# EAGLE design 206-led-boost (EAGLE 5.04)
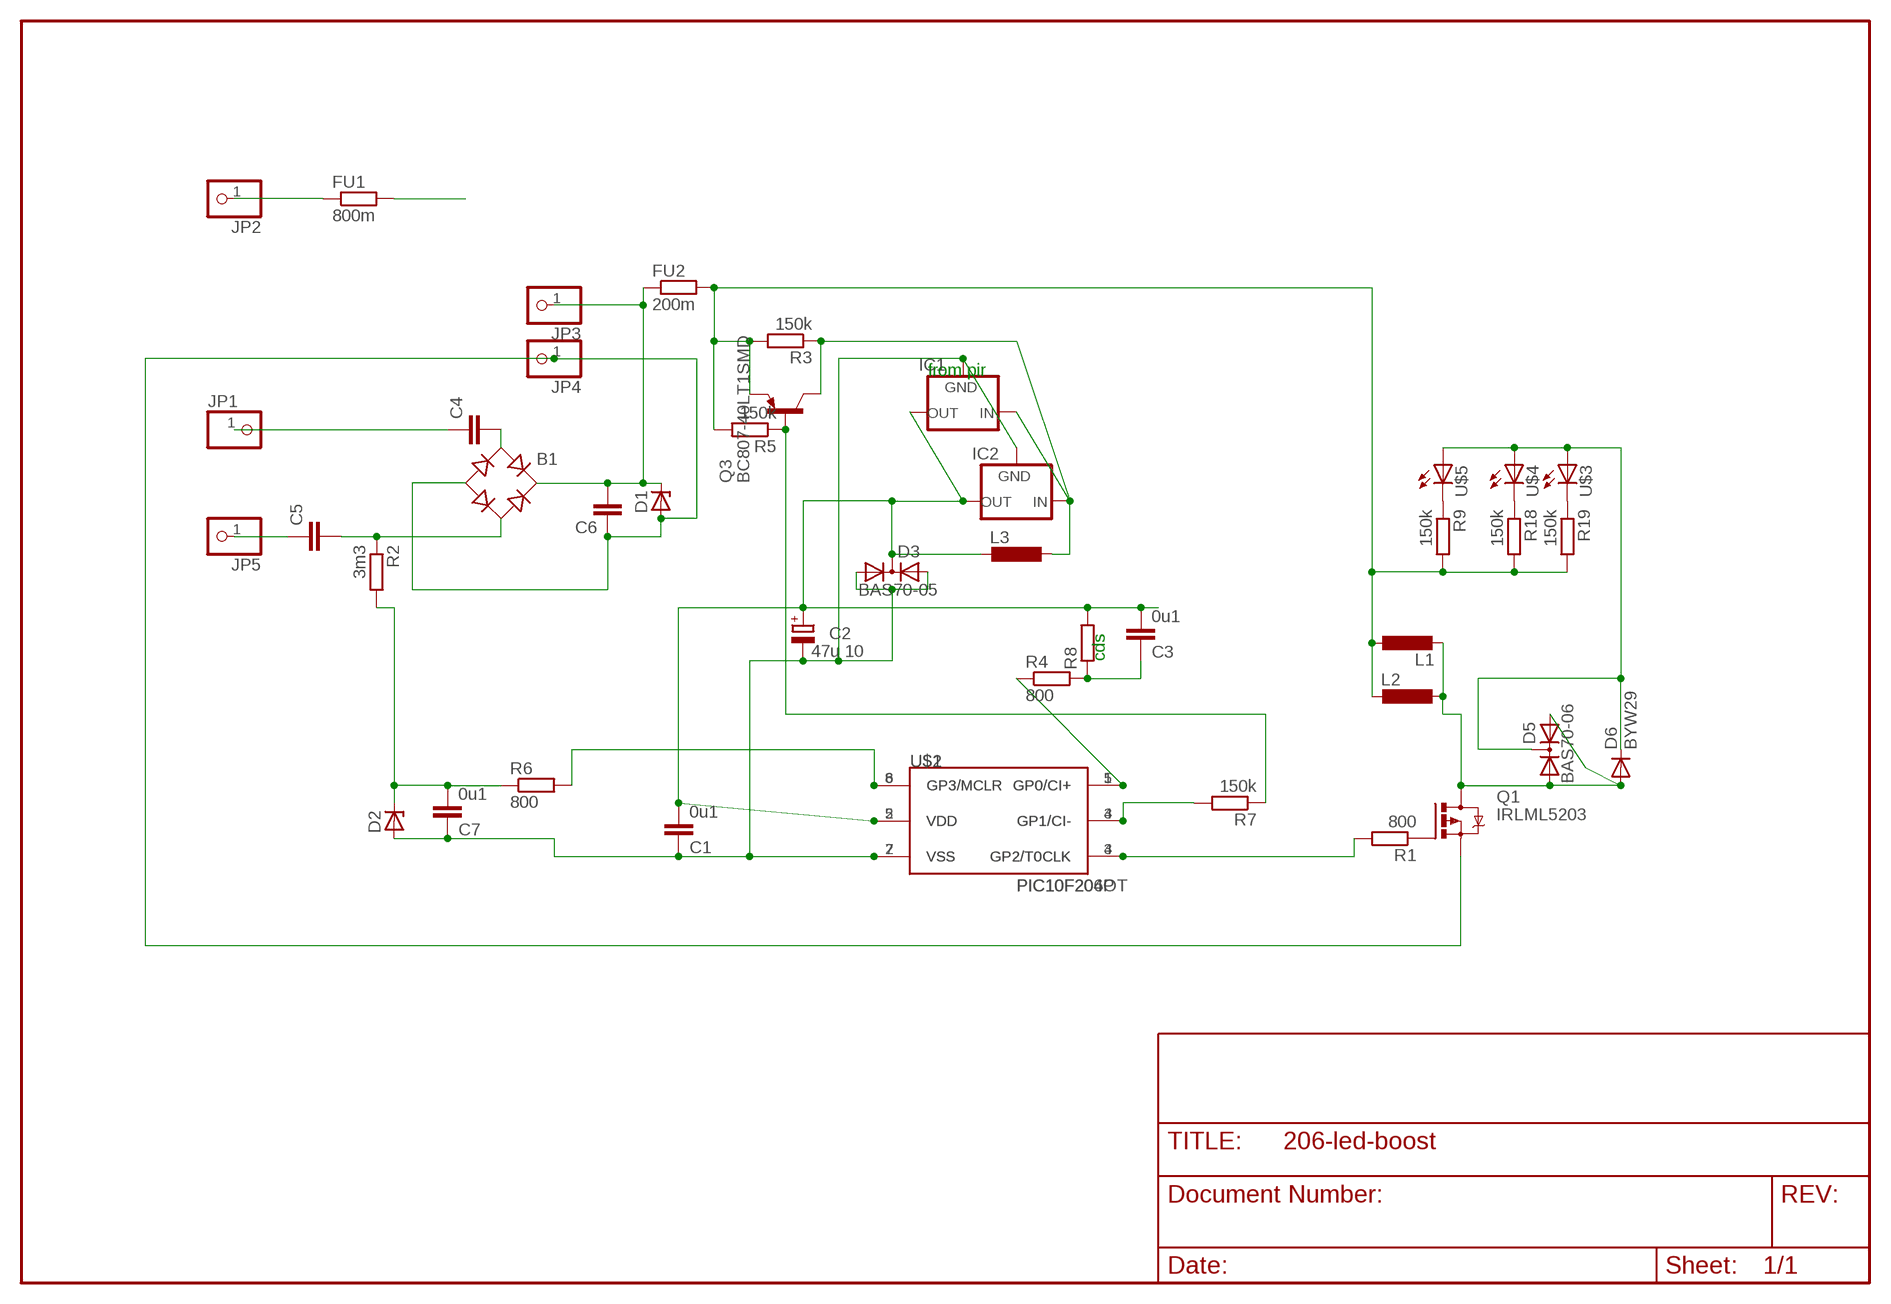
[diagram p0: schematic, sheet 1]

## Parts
B1  RB1A  [RB1A]
C1  0u1  C-EUC1206  [C1206]
C2  47u 10  CPOL-EUE2.5-5  [E2,5-5]
C3  0u1  C-EUC1206  [C1206]
C4  C-EU050-025X075  [C050-025X075]
C5  C-EU050-025X075  [C050-025X075]
C6  C-EU050-025X075  [C050-025X075]
C7  0u1  C-EUC1206  [C1206]
D1  ZENER-DIODEZD-7.5  [ZDIO-7.5]
D2  ZENER-DIODESOT23  [SOT23]
D3  BAS70-05  [SOT23]
D5  BAS70-06  [SOT23]
D6  BYW29  [DO220S]
FU1  800m  R-EU_0204/5  [0204/5]
FU2  200m  R-EU_0204/5  [0204/5]
IC1  XC63FPT  [TO92]
IC2  XC63FPP  [SOT89R]
JP1  PINHD-1X1  [1X01]
JP2  PINHD-1X1  [1X01]
JP3  PINHD-1X1  [1X01]
JP4  PINHD-1X1  [1X01]
JP5  PINHD-1X1  [1X01]
L1  L-EUL5650M  [L5650M]
L2  L-EU0207/7  [0207/7]
L3  L-EU0207/7  [0207/7]
Q1  IRLML5203  [MICRO3]
Q3  BC807-40LT1SMD  [SOT23-BEC]
R1  800  R-EU_R1206  [R1206]
R2  3m3  R-EU_R1206  [R1206]
R3  150k  R-EU_R1206  [R1206]
R4  800  R-EU_R1206  [R1206]
R5  150k  R-EU_R1206  [R1206]
R6  800  R-EU_R1206  [R1206]
R7  150k  R-EU_R1206  [R1206]
R8  R-EU_0207/5V  [0207/5V]
R9  150k  R-EU_R1206  [R1206]
R18  150k  R-EU_R1206  [R1206]
R19  150k  R-EU_R1206  [R1206]
U$1  PIC10F206P  [DIL8]
U$2  PIC10F204OT  [SOT23-6]
U$3  LED5MM  [LED5MM]
U$4  LED5MM  [LED5MM]
U$5  LED5MM  [LED5MM]

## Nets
N$1: B1.+ C6.2 D1.C FU2.1 JP3.1
N$4: FU1.1 JP2.1
N$6: C1.1 C2.- C7.1 D2.1(A) D3.1(A1) D3.2(A2) IC1.1(GND) IC2.1(GND) U$1.7(VSS) U$2.2(VSS)
N$7: D5.3(C) D6.C U$3.A U$4.A U$5.A
N$8: B1.- C6.1 D1.A JP4.1 Q1.2(S)
N$9: FU1.2
N$10: Q1.1(G) R1.1
N$11: Q3.B R5.1 R7.1
N$12: R6.2 U$1.8(GP3/MCLR) U$2.6(GP3/MCLR)
N$13: R7.2 U$1.4(GP1/CI-) U$2.3(GP1/CI-)
N$14: R1.2 U$1.3(GP2/T0CLK) U$2.4(GP2/T0CLK)
N$15: IC1.2(IN) IC2.2(IN) L3.1 Q3.C R3.1
N$16: C7.2 D2.3(C) R2.2 R6.1
N$17: C5.1 JP5.1
N$18: B1.AC2 C5.2 R2.1
N$19: FU2.2 L1.1 L2.2 Q3.E R3.2 R5.2 R9.2 R18.2 R19.2
N$20: C4.1 JP1.1
N$23: C3.1 R4.2 R8.1
N$26: D5.1(A1) D5.2(A2) D6.A L1.2 L2.1 Q1.3(D)
N$29: R4.1 U$1.5(GP0/CI+) U$2.1(GP0/CI+)
N$33: B1.AC1 C4.2
N$38: R9.1 U$5.K(C)
N$54: R18.1 U$4.K(C)
N$55: R19.1 U$3.K(C)
V2CC: C1.2 C2.+ C3.2 D3.3(C) IC1.3(OUT) IC2.3(OUT) L3.2 R8.2 U$1.2(VDD) U$2.5(VDD)

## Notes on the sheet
- from pir
- cds

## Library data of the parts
B1 = rectifier:RB1A: RECTIFIER 1 A
C1 C3-C7 = rcl:C-EU: CAPACITOR, European symbol
C2 = rcl:CPOL-EU: POLARIZED CAPACITOR, European symbol
D1 D2 = diode-1:ZENER-DIODE: Z-Diode
D3 = diode-1:BAS70-05: Silicon Schottky Diodes General-purpose diode for high-speed switching
D5 = diode-1:BAS70-06: Silicon Schottky Diodes General-purpose diode for high-speed switching
D6 = diode:BYW29: DIODE
FU1 FU2 R1-R7 R9 R18 R19 = rcl:R-EU_: RESISTOR, European symbol
IC1 IC2 = v-reg:XC63FP: Positiv Voltage Regulators www.torex.co.jp/english/product/pro02/pdf/0201_xc62fp.pdf
JP1-JP5 = pinhead:PINHD-1X1: PIN HEADER
L1 = rcl-2:L-EU: INDUCTOR, European symbol
L2 L3 = rcl:L-EU: INDUCTOR, European symbol
Q1 = transistor-power:IRLML5203: HEXFET P-Channel Power MOSFET
Q3 = transistor-pnp:BC807*: PNP Transistror
R8 = rcl(2):R-EU_: RESISTOR, European symbol
U$1 U$2 = microchip-3:PIC10F2*: uPC nW 0,25/0,5k Program Flash memory Comparator
U$3-U$5 = led(3):LED: LED

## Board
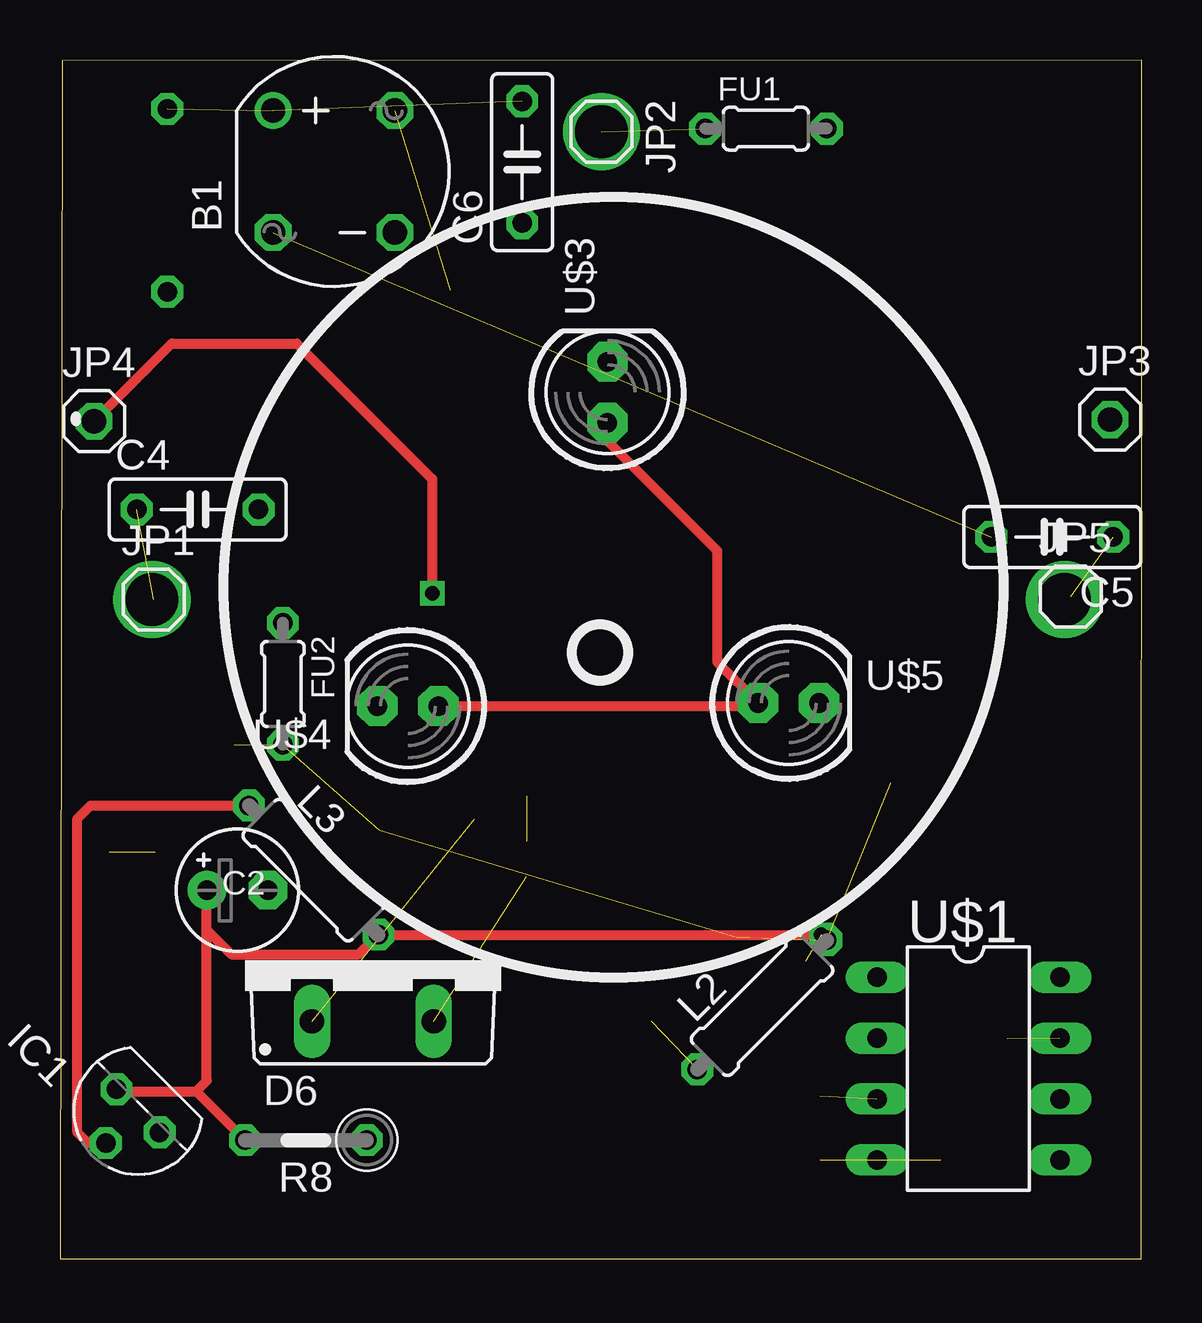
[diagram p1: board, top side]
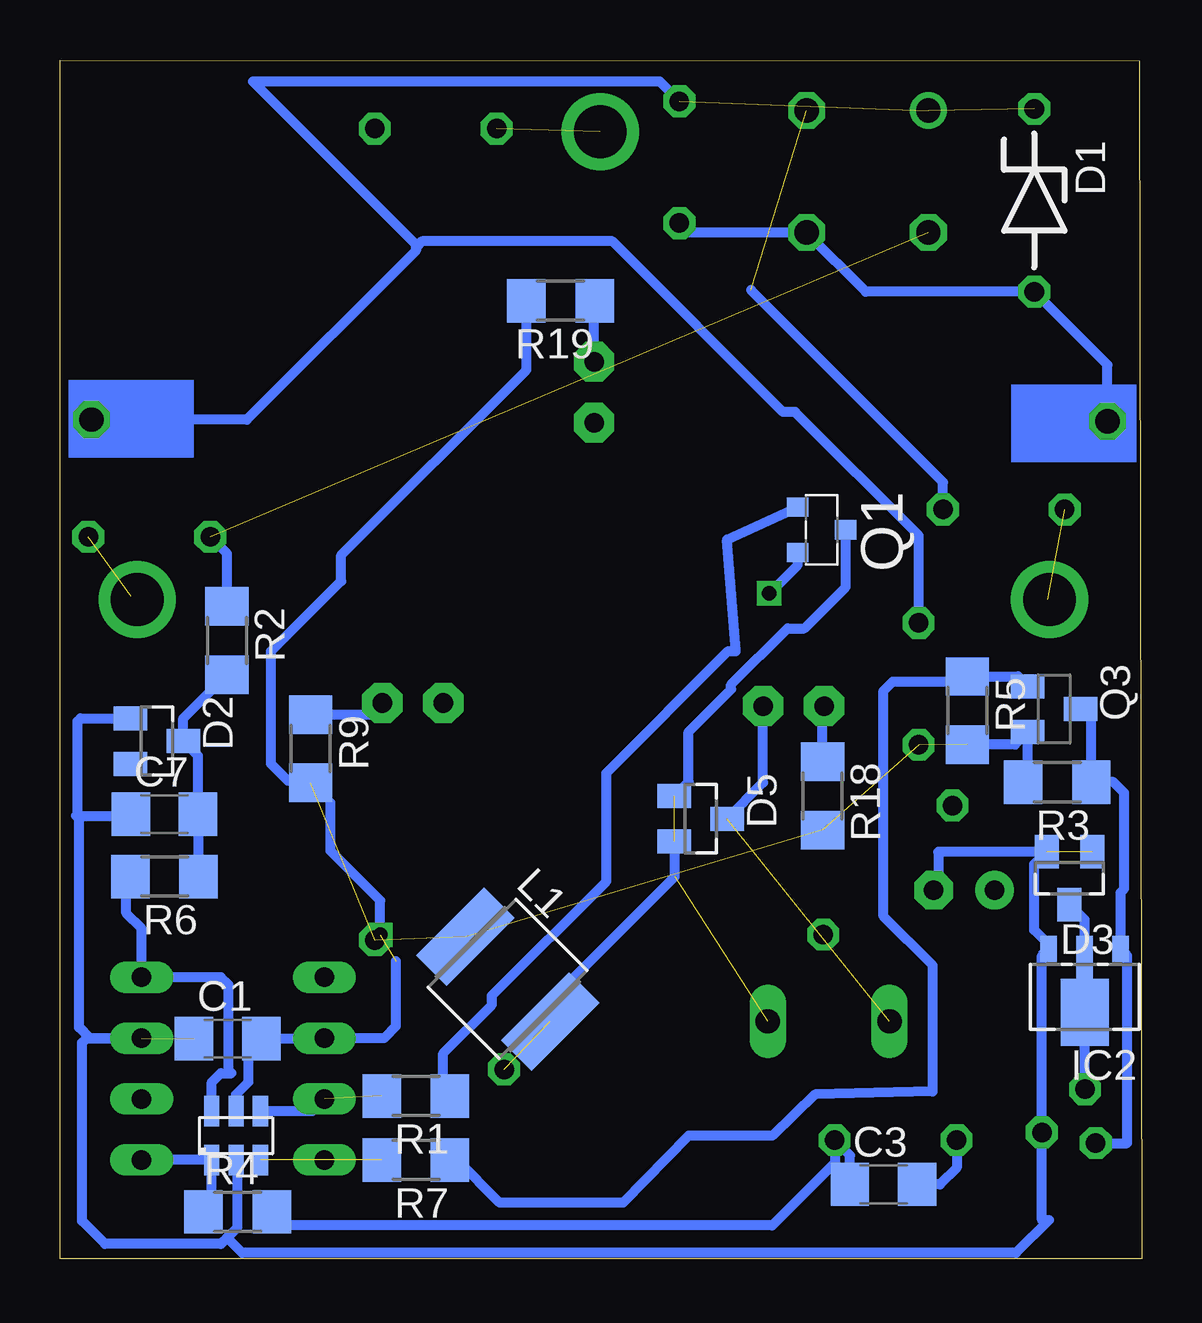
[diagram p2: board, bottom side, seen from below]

Size 45.09 x 49.97 mm. Coordinates in mm from the lower left corner, seen from the top.
Outline: 0,0 45.07,0 45.08,49.97 0.09,49.94 0,0
Copper layers (1*16): Top 0.035mm / dielectric 1.5mm / Bottom 0.035mm
Design rules "default": minimum track width 10mil, minimum drill 24mil, track to track 8mil, track to pad 8mil, pad to pad 8mil, via to via 8mil, smd to smd 8mil, copper to edge 40mil, drill to drill 8mil, minimum pad ring 10mil, minimum via ring 8mil, stop-mask expansion 4mil, vias tented up to drill 0mil, thermal gap 10mil

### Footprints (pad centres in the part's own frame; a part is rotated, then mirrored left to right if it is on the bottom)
RB1A = drill 1.016 round: + -2.54,2.54 | drill 1.016 octagon: - 2.54,-2.54; AC1 2.54,2.54; AC2 -2.54,-2.54
C1206 = smd 1.6 x 1.8: 1 -1.4,0; 2 1.4,0
E2,5-5 = drill 0.813 pad 1.6 round: + -1.27,0 | drill 0.813 pad 1.6 octagon: - 1.27,0
C050-025X075 = drill 0.813 octagon: 1 -2.54,0; 2 2.54,0
ZDIO-7.5 = drill 0.813 octagon: A 3.81,0; C -3.81,0
SOT23 = smd 1 x 1.4: 1 -0.95,-1.1; 2 0.95,-1.1; 3 0,1.1
DO220S = drill 1.016 long: A 2.54,-2.54; C -2.54,-2.54
0204/5 = drill 0.813 octagon: 1 -2.54,0; 2 2.54,0
TO92 = drill 0.813 octagon: 1 -1.27,0; 2 0,1.905; 3 1.27,0
SOT89R = smd 0.7 x 1.1: 1 1.5,-1.75; 2 -1.5,-1.75 | smd 0.7 x 1.8: 3 0,-1.4 | smd 2 x 2.8: 4 0,0.9
1X01 = drill 1.016 octagon: 1 0,0
L5650M = smd 1.8 x 4: 1 -2.5,0; 2 2.5,0
0207/7 = drill 0.813 octagon: 1 -3.81,0; 2 3.81,0
MICRO3 = smd 0.8 x 0.9: 1 -0.95,-1; 2 0.95,-1; 3 0,1
SOT23-BEC = smd 1 x 1.4: B -0.95,-1.1; C 0,1.1; E 0.95,-1.1
R1206 = smd 1.6 x 1.803: 1 -1.422,0; 2 1.422,0
0207/5V = drill 0.813 octagon: 1 -2.54,0; 2 2.54,0
DIL8 = drill 0.813 long: 1 -3.81,-3.81; 2 -1.27,-3.81; 3 1.27,-3.81; 4 3.81,-3.81; 5 3.81,3.81; 6 1.27,3.81; 7 -1.27,3.81; 8 -3.81,3.81
SOT23-6 = smd 0.635 x 1.27: 1 -1.016,-1.016; 2 0,-1.016; 3 1.016,-1.016; 4 1.016,1.016; 5 0,1.016; 6 -1.016,1.016
LED5MM = drill 0.813 pad 1.676 octagon: A -1.27,0; K 1.27,0

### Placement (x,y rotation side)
B1  11.43,45.33 0 top
C1  38.09,9.18 0 bottom
C2  7.39,15.36 0 top
C3  10.76,3.11 0 bottom
C4  5.74,31.24 0 top
C5  41.36,30.09 180 top
C6  19.27,45.71 90 top
C7  40.73,18.54 0 bottom
D1  4.47,44.13 270 bottom
D2  41.05,21.59 270 bottom
D3  3.01,15.87 180 bottom
D5  18.38,18.35 270 bottom
D6  13.04,12.44 0 top
FU1  29.43,47.11 0 top
FU2  9.29,23.97 270 top
IC1  3.26,6.17 135 top
IC2  2.38,11.17 180 bottom
JP1  3.9,27.49 0 top
JP2  22.57,46.98 270 top
JP3  43.78,34.98 0 top
JP4  1.42,34.92 0 top
JP5  42.13,27.62 0 top
L1  26.42,11.66 315 bottom
L2  29.27,10.59 45 top
L3  10.57,16.21 315 top
Q1  13.33,30.39 270 bottom
Q3  3.65,22.92 270 bottom
R1  30.25,6.79 180 bottom
R2  38.13,25.78 270 bottom
R3  3.52,19.87 180 bottom
R4  37.68,1.96 0 bottom
R5  7.26,22.86 270 bottom
R6  40.73,15.93 180 bottom
R7  30.25,4.12 180 bottom
R8  10.25,4.95 180 top
R9  34.63,21.27 270 bottom
R18  13.3,19.3 270 bottom
R19  24.22,39.94 180 bottom
U$1  37.87,7.93 270 top
U$2  37.74,5.14 0 bottom
U$3  22.82,36.13 90 top
U$4  14.5,23.05 180 top
U$5  30.38,23.17 0 top

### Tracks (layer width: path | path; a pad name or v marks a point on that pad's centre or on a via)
N$1  (2 unrouted)
  Bottom 0.406: JP3.1 37.3,34.98 30.25,42.03 30.25,42.16 | 30.25,42.16 30.25,42.29 37.05,49.08 20.09,49.08 C6.2 | FU2.1 9.29,30.15 14.44,35.3 14.95,35.3 22.06,42.41 30,42.41 30.25,42.16
N$2  (via drill 2.2)
  other vias: 3.84,27.49
N$3  (via drill 2.2)
  other vias: 41.87,27.49
N$4  (1 unrouted)
N$5  (via drill 2.2)
  other vias: 22.57,46.98
N$6  (2 unrouted)
  Bottom 0.406: 38.13,0.88 37.68,1.33 37.68,4.06 U$2.2 | 38.13,0.88 38.38,0.63 43.21,0.63 44.16,1.58 44.16,9.01 43.97,9.2 U$1.7 43.84,9.2 44.29,9.65 44.29,18.47 | 38.13,0.88 37.49,0.25 5.23,0.25 3.85,1.63 4.15,1.63 IC1.1 4.15,12.64 IC2.1 3.87,13.11 4.47,13.71 4.47,16.46 D3.2 8.45,16.97 8.47,16.95 8.47,15.55 C2.- | D2.1 44.22,22.54 44.35,22.41 44.35,18.54 44.41,18.47 44.29,18.47 | 44.29,18.47 42.19,18.47 C7.1
N$7  (1 unrouted)
  Top 0.406: U$4.A 28.98,23.05 U$5.A 27.39,24.89 27.39,29.52 22.82,34.09 U$3.A
  Bottom 0.406: U$4.A 15.77,19.85 D5.3
N$8  (via drill 0.6)
  Top 0.406: v15.52,27.75 15.52,32.51 9.87,38.16 4.66,38.16 JP4.1
  Bottom 0.406: JP4.1 1.42,37.27 D1.A 11.5,40.32 B1.- 18.88,42.79 C6.1 | Q1.2 14.33,28.93 v15.52,27.75
N$10
  Bottom 0.406: Q1.1 17.28,29.98 16.92,25.33 17.23,25.33 22.31,20.25 22.31,15.74 27.08,10.98 27.08,10.6 29.11,8.57 29.11,7.07 R1.1
N$11
  Bottom 0.406: R7.1 28.54,4.12 26.76,2.34 21.62,2.34 18.89,5.14 15.39,5.14 13.61,6.85 8.7,6.98 8.7,12.23 10.76,14.28 10.76,23.68 10.38,24.06 7.92,24.06 R5.1 5.15,24.28 Q3.B
N$12
  Bottom 0.406: U$2.6 38.76,7.36 38.38,7.74 37.94,7.74 38.06,7.87 38.06,11.42 38.38,11.74 U$1.8 41.68,13.77 42.32,14.41 42.32,15.77 R6.2
N$13  (2 unrouted)
N$14  (1 unrouted)
  Bottom 0.406: U$2.4 34.57,6.16 U$1.3
N$15
  Top 0.406: L3.1 1.28,18.9 0.72,18.35 0.72,5.27 1.17,4.83 IC1.2
  Bottom 0.406: IC1.2 0.6,4.83 0.6,12.64 IC2.2 0.88,15.27 0.72,15.43 0.72,19.43 1.17,19.87 R3.1 2.1,22.47 Q3.C
N$16
  Bottom 0.406: R6.1 39.31,18.52 C7.2 39.33,20.97 D2.3 39.95,22.53 R2.2
N$17  (1 unrouted)
N$18  (1 unrouted)
  Bottom 0.406: R2.1 38.13,29.4 C5.2
N$19  (5 unrouted)
  Bottom 0.406: R5.2 5.28,21.43 Q3.E 4.75,20.07 R3.2 | R19.2 25.64,37.05 33.36,29.33 33.36,28.25 36.28,25.33 36.28,20.63 35.59,19.93 34.72,19.93 R9.2
N$20  (1 unrouted)
N$23
  Bottom 0.406: C3.1 12.16,4.32 R8.1 12.79,4 15.39,1.39 35.69,1.39 R4.2
N$26  (3 unrouted)
  Bottom 0.406: L1.2 24.65,10.74 19.46,15.93 19.46,17.38 D5.2 | Q1.3 12.33,28.01 14.06,26.28 14.76,26.28 17.11,23.93 17.11,23.74 18.89,21.97 18.89,19.89 D5.1
N$29
  Bottom 0.406: U$1.5 U$2.1 38.76,2.31 R4.1
N$33  (1 unrouted)
  Bottom 0.406: C4.2 8.28,32.38 16.28,40.38
N$38
  Bottom 0.406: R9.1 32.13,22.69 U$5.K
N$54
  Bottom 0.406: R18.1 13.3,22.98 U$4.K
N$55
  Bottom 0.406: U$3.K 22.82,39.91 R19.1
V2CC  (via drill 0.6)  (1 unrouted)
  Top 0.406: 6.12,13.71 7.14,12.69 12.45,12.69 L3.2 v31.73,13.51 | 5.68,6.98 R8.2 | 5.68,6.98 2.45,6.98 IC1.3 | 6.12,13.71 6.12,7.42 5.68,6.98 | 6.12,13.71 C2.+
  Bottom 0.406: U$2.5 37.74,6.85 37.24,7.36 37.24,8.64 C1.2 34.08,9.18 U$1.2 31.58,9.2 31.08,9.71 31.08,12.4 | D3.3 2.37,14.13 IC2.3 2.36,12.55 IC1.3 | C3.2 8.41,3.11 7.71,3.81 R8.2 | v31.73,13.51 31.73,14.94 33.81,17.01 33.81,19.02 | L3.2 13.3,13.54
(copper drawn outside any net)
  shapes: Bottom area x2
